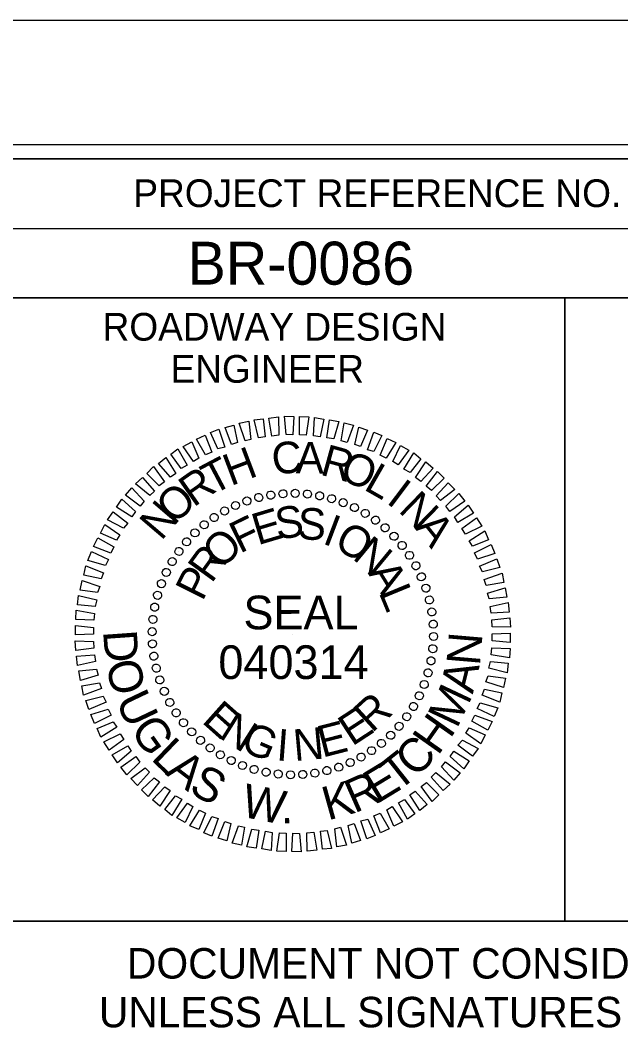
# Model space of a CAD drawing. Extents: x 10070 to 15319, y 8517 to 10343.
# Drawn here: x 14676.7 to 14785, y 9432.8 to 9616.7 of the extents above; entities that cross this region are included whole.
import ezdxf

# ---------------------------------------------------------------- set-up
doc = ezdxf.new("R2010")
doc.units = 0
for name, color, linetype in [('Scratch_Level_3', 7, 'Continuous'), ('Scratch_Level_4', 7, 'Continuous'), ('Sheet Cutting Line CELL', 7, 'Continuous'), ('Sheet Data Field CELL', 7, 'Continuous'), ('Sheet PE Seal Cell', 7, 'Continuous'), ('Sheet Plot Border Inside CELL', 7, 'Continuous'), ('Sheet Plot Border Outside CELL', 7, 'Continuous'), ('Sheet Profile CELL', 7, 'Continuous'), ('Sheet Profile Grid Major CELL', 7, 'Continuous'), ('Sheet Profile Grid Minor CELL', 7, 'Continuous'), ('Sheet Sticker Exception Certification CELL', 7, 'Continuous')]:
    doc.layers.add(name, color=color, linetype=linetype)

msp = doc.modelspace()

# ---------------------------------------------------------------- linework, layer by layer
at = {"layer": 'Scratch_Level_3'}
msp.add_lwpolyline([(13374.94, 9591.73), (14824.91, 9591.73), (14824.91, 8566.73), (13374.94, 8566.73)], close=True, dxfattribs=at)
at = {"layer": 'Scratch_Level_4'}
msp.add_lwpolyline([(13374.94, 9591.73), (14874.94, 9591.73), (14874.94, 9091.73), (13374.94, 9091.73)], close=True, dxfattribs=at)
at = {"layer": 'Sheet Cutting Line CELL'}
msp.add_line((14891.94, 9616.73), (13207.94, 9616.73), dxfattribs=at)
at = {"layer": 'Sheet PE Seal Cell'}
for p, q in [((14719.69, 9530.65), (14719.69, 9530.65)), ((14721.92, 9531.05), (14721.92, 9531.05)), ((14724.1, 9531.36), (14724.1, 9531.36)), ((14726.33, 9531.41), (14726.33, 9531.41)), ((14728.55, 9531.26), (14728.55, 9531.26)), ((14730.73, 9530.9), (14730.73, 9530.9)), ((14732.86, 9530.45), (14732.86, 9530.45)), ((14715.54, 9529.23), (14715.54, 9529.23)), ((14717.57, 9530.04), (14717.57, 9530.04)), ((14734.98, 9529.74), (14734.98, 9529.74)), ((14737.01, 9528.83), (14737.01, 9528.83)), ((14711.65, 9527.05), (14711.65, 9527.05)), ((14713.57, 9528.21), (14713.57, 9528.21)), ((14738.98, 9527.82), (14738.98, 9527.82)), ((14709.88, 9525.78), (14709.88, 9525.78)), ((14740.81, 9526.55), (14740.81, 9526.55)), ((14742.58, 9525.19), (14742.58, 9525.19)), ((14708.21, 9524.26), (14708.21, 9524.26)), ((14744.15, 9523.67), (14744.15, 9523.67)), ((14706.69, 9522.69), (14706.69, 9522.69)), ((14745.67, 9522), (14745.67, 9522)), ((14705.32, 9520.92), (14705.32, 9520.92)), ((14746.93, 9520.23), (14746.93, 9520.23)), ((14704.06, 9519.1), (14704.06, 9519.1)), ((14748.1, 9518.3), (14748.1, 9518.3)), ((14703.04, 9517.12), (14703.04, 9517.12)), ((14749.11, 9516.33), (14749.11, 9516.33)), ((14702.13, 9515.1), (14702.13, 9515.1)), ((14749.92, 9514.31), (14749.92, 9514.31)), ((14701.43, 9512.97), (14701.43, 9512.97)), ((14750.53, 9512.18), (14750.53, 9512.18)), ((14700.97, 9510.84), (14700.97, 9510.84)), ((14700.62, 9508.67), (14700.62, 9508.67)), ((14750.94, 9509.95), (14750.94, 9509.95)), ((14700.47, 9506.44), (14700.47, 9506.44)), ((14751.24, 9507.78), (14751.24, 9507.78)), ((14725.88, 9505.99), (14725.88, 9505.99)), ((14751.29, 9505.55), (14751.29, 9505.55)), ((14700.52, 9504.21), (14700.52, 9504.21)), ((14751.14, 9503.32), (14751.14, 9503.32)), ((14700.82, 9502.03), (14700.82, 9502.03)), ((14750.79, 9501.14), (14750.79, 9501.14)), ((14701.23, 9499.81), (14701.23, 9499.81)), ((14701.84, 9497.68), (14701.84, 9497.68)), ((14750.34, 9499.02), (14750.34, 9499.02)), ((14702.65, 9495.66), (14702.65, 9495.66)), ((14749.63, 9496.89), (14749.63, 9496.89)), ((14703.66, 9493.68), (14703.66, 9493.68)), ((14748.72, 9494.87), (14748.72, 9494.87)), ((14704.83, 9491.76), (14704.83, 9491.76)), ((14747.71, 9492.89), (14747.71, 9492.89)), ((14706.09, 9489.99), (14706.09, 9489.99)), ((14746.44, 9491.07), (14746.44, 9491.07)), ((14707.61, 9488.32), (14707.61, 9488.32)), ((14745.07, 9489.3), (14745.07, 9489.3)), ((14709.18, 9486.8), (14709.18, 9486.8)), ((14741.89, 9486.21), (14741.89, 9486.21)), ((14743.56, 9487.72), (14743.56, 9487.72)), ((14710.95, 9485.43), (14710.95, 9485.43)), ((14740.12, 9484.94), (14740.12, 9484.94)), ((14712.78, 9484.17), (14712.78, 9484.17)), ((14714.75, 9483.16), (14714.75, 9483.16)), ((14736.22, 9482.76), (14736.22, 9482.76)), ((14738.19, 9483.77), (14738.19, 9483.77)), ((14716.78, 9482.25), (14716.78, 9482.25)), ((14718.9, 9481.54), (14718.9, 9481.54)), ((14721.03, 9481.08), (14721.03, 9481.08)), ((14723.21, 9480.73), (14723.21, 9480.73)), ((14729.84, 9480.94), (14729.84, 9480.94)), ((14732.07, 9481.34), (14732.07, 9481.34)), ((14734.19, 9481.95), (14734.19, 9481.95)), ((14725.44, 9480.58), (14725.44, 9480.58)), ((14727.66, 9480.63), (14727.66, 9480.63))]:
    msp.add_line(p, q, dxfattribs=at)
for points in [[(14722.12, 9541.73), (14721.56, 9544.97), (14723.28, 9545.18), (14723.33, 9541.89)], [(14724.65, 9541.99), (14724.4, 9545.28), (14726.07, 9545.23), (14725.87, 9541.94)], [(14727.08, 9541.94), (14727.08, 9545.23), (14728.75, 9545.18), (14728.3, 9541.89)], [(14729.61, 9541.79), (14729.81, 9545.08), (14731.48, 9544.77), (14730.83, 9541.58)], [(14714.83, 9540.21), (14713.66, 9543.25), (14715.23, 9543.7), (14715.89, 9540.57)], [(14717.26, 9540.87), (14716.2, 9544.06), (14717.92, 9544.41), (14718.32, 9541.12)], [(14719.69, 9541.43), (14718.88, 9544.67), (14720.55, 9544.82), (14720.9, 9541.58)], [(14732.04, 9541.38), (14732.5, 9544.62), (14734.17, 9544.37), (14733.26, 9541.23)], [(14734.62, 9540.83), (14735.13, 9544.12), (14736.85, 9543.71), (14735.69, 9540.57)], [(14737.05, 9540.17), (14737.81, 9543.31), (14739.38, 9542.8), (14738.12, 9539.82)], [(14710.12, 9538.34), (14708.5, 9541.17), (14710.07, 9541.88), (14711.24, 9538.79)], [(14712.35, 9539.4), (14711.03, 9542.34), (14712.55, 9542.94), (14713.62, 9539.7)], [(14739.33, 9539.26), (14740.5, 9542.45), (14741.91, 9541.84), (14740.5, 9538.91)], [(14707.95, 9537.12), (14706.07, 9539.85), (14707.64, 9540.66), (14708.91, 9537.73)], [(14741.61, 9538.3), (14742.88, 9541.29), (14744.45, 9540.58), (14742.73, 9537.74)], [(14743.94, 9537.14), (14745.31, 9540.02), (14746.83, 9539.16), (14744.9, 9536.53)], [(14703.8, 9534.33), (14701.62, 9536.76), (14702.99, 9537.83), (14704.76, 9534.99)], [(14705.72, 9535.85), (14703.85, 9538.43), (14705.16, 9539.4), (14706.83, 9536.46)], [(14745.92, 9535.77), (14747.69, 9538.71), (14749, 9537.64), (14747.03, 9535.16)], [(14701.77, 9532.76), (14699.54, 9534.99), (14700.76, 9536.21), (14702.73, 9533.47)], [(14747.99, 9534.25), (14749.86, 9537.04), (14751.18, 9535.92), (14748.95, 9533.54)], [(14700.1, 9530.99), (14697.52, 9533.07), (14698.78, 9534.23), (14700.91, 9531.8)], [(14749.92, 9532.68), (14751.99, 9535.32), (14753.21, 9534.1), (14750.88, 9531.92)], [(14698.33, 9529.07), (14695.7, 9531.04), (14696.81, 9532.36), (14699.04, 9529.98)], [(14751.74, 9530.91), (14753.92, 9533.29), (14755.13, 9532.08), (14752.5, 9530.1)], [(14696.81, 9527.14), (14694.08, 9528.86), (14695.04, 9530.33), (14697.47, 9528.1)], [(14753.51, 9529.09), (14755.84, 9531.37), (14756.9, 9530), (14754.22, 9528.08)], [(14755.03, 9527.12), (14757.51, 9529.24), (14758.47, 9527.78), (14755.64, 9526.15)], [(14695.3, 9525.12), (14692.46, 9526.63), (14693.47, 9528.05), (14696.11, 9526.03)], [(14756.35, 9525.04), (14759.03, 9526.97), (14759.99, 9525.45), (14757.06, 9524.03)], [(14694.08, 9522.94), (14691.2, 9524.2), (14691.95, 9525.77), (14694.69, 9523.9)], [(14693.07, 9520.61), (14689.93, 9521.77), (14690.69, 9523.34), (14693.58, 9521.72)], [(14757.67, 9522.81), (14760.5, 9524.59), (14761.16, 9523.02), (14758.27, 9521.85)], [(14758.68, 9520.64), (14761.67, 9522.16), (14762.32, 9520.54), (14759.19, 9519.52)], [(14692.06, 9518.38), (14688.92, 9519.29), (14689.58, 9520.86), (14692.61, 9519.45)], [(14759.59, 9518.26), (14762.68, 9519.58), (14763.24, 9518.01), (14760.1, 9517.2)], [(14691.3, 9515.95), (14688.16, 9516.61), (14688.51, 9518.28), (14691.7, 9517.02)], [(14690.64, 9513.52), (14687.5, 9513.93), (14687.86, 9515.65), (14691.05, 9514.59)], [(14760.4, 9515.83), (14763.64, 9516.99), (14763.95, 9515.32), (14760.76, 9514.77)], [(14761.01, 9513.4), (14764.2, 9514.36), (14764.5, 9512.64), (14761.32, 9512.34)], [(14690.24, 9510.94), (14687, 9511.24), (14687.2, 9512.96), (14690.49, 9512.15)], [(14689.99, 9508.51), (14686.7, 9508.61), (14686.8, 9510.28), (14690.09, 9509.72)], [(14761.47, 9510.97), (14764.76, 9511.68), (14764.91, 9509.96), (14761.67, 9509.75)], [(14761.77, 9508.54), (14765.06, 9508.95), (14765.17, 9507.22), (14761.87, 9507.32)], [(14689.94, 9505.98), (14686.65, 9505.83), (14686.65, 9507.55), (14689.94, 9507.19)], [(14689.99, 9503.45), (14686.7, 9503.04), (14686.6, 9504.76), (14689.89, 9504.66)], [(14761.82, 9506.01), (14765.12, 9506.16), (14765.12, 9504.44), (14761.83, 9504.79)], [(14761.77, 9503.48), (14765.07, 9503.38), (14764.97, 9501.71), (14761.67, 9502.26)], [(14690.29, 9501.02), (14687, 9500.31), (14686.85, 9502.03), (14690.09, 9502.23)], [(14761.52, 9501.05), (14764.76, 9500.74), (14764.56, 9499.02), (14761.27, 9499.83)], [(14690.75, 9498.59), (14687.56, 9497.62), (14687.26, 9499.35), (14690.45, 9499.65)], [(14691.36, 9496.16), (14688.12, 9494.99), (14687.81, 9496.66), (14691, 9497.22)], [(14761.12, 9498.46), (14764.26, 9498.06), (14763.9, 9496.34), (14760.71, 9497.4)], [(14760.46, 9496.03), (14763.6, 9495.38), (14763.25, 9493.71), (14760.06, 9494.97)], [(14692.17, 9493.73), (14689.08, 9492.41), (14688.52, 9493.98), (14691.66, 9494.79)], [(14759.7, 9493.6), (14762.84, 9492.69), (14762.19, 9491.12), (14759.15, 9492.54)], [(14693.08, 9491.35), (14690.1, 9489.83), (14689.44, 9491.45), (14692.58, 9492.46)], [(14694.1, 9489.17), (14691.26, 9487.4), (14690.6, 9488.97), (14693.49, 9490.13)], [(14758.69, 9491.38), (14761.83, 9490.21), (14761.07, 9488.64), (14758.19, 9490.26)], [(14757.68, 9489.05), (14760.57, 9487.78), (14759.81, 9486.21), (14757.07, 9488.08)], [(14695.41, 9486.95), (14692.73, 9485.02), (14691.77, 9486.54), (14694.7, 9487.96)], [(14756.47, 9486.87), (14759.3, 9485.35), (14758.29, 9483.93), (14755.66, 9485.96)], [(14696.73, 9484.87), (14694.25, 9482.74), (14693.29, 9484.21), (14696.12, 9485.83)], [(14754.95, 9484.84), (14757.68, 9483.12), (14756.72, 9481.66), (14754.29, 9483.88)], [(14698.25, 9482.9), (14695.92, 9480.62), (14694.86, 9481.98), (14697.54, 9483.91)], [(14753.43, 9482.92), (14756.06, 9480.95), (14754.95, 9479.63), (14752.72, 9482.01)], [(14700.02, 9481.08), (14697.85, 9478.69), (14696.63, 9479.91), (14699.26, 9481.88)], [(14751.66, 9481), (14754.24, 9478.92), (14752.98, 9477.76), (14750.85, 9480.18)], [(14701.84, 9479.3), (14699.77, 9476.67), (14698.55, 9477.89), (14700.88, 9480.06)], [(14749.99, 9479.22), (14752.22, 9477), (14751, 9475.78), (14749.03, 9478.51)], [(14703.77, 9477.74), (14701.9, 9474.95), (14700.58, 9476.06), (14702.81, 9478.44)], [(14747.96, 9477.65), (14750.14, 9475.22), (14748.78, 9474.16), (14747, 9476.99)], [(14705.85, 9476.22), (14704.07, 9473.28), (14702.76, 9474.34), (14704.73, 9476.82)], [(14707.82, 9474.85), (14706.45, 9471.97), (14704.94, 9472.83), (14706.86, 9475.46)], [(14746.04, 9476.13), (14747.92, 9473.55), (14746.6, 9472.59), (14744.93, 9475.52)], [(14710.15, 9473.69), (14708.89, 9470.7), (14707.32, 9471.41), (14709.04, 9474.24)], [(14741.64, 9473.65), (14743.26, 9470.82), (14741.69, 9470.11), (14740.52, 9473.19)], [(14743.81, 9474.87), (14745.69, 9472.13), (14744.12, 9471.32), (14742.85, 9474.26)], [(14712.43, 9472.73), (14711.27, 9469.54), (14709.85, 9470.14), (14711.26, 9473.08)], [(14714.71, 9471.82), (14713.95, 9468.68), (14712.38, 9469.18), (14713.64, 9472.17)], [(14736.93, 9471.78), (14738.1, 9468.74), (14736.53, 9468.28), (14735.87, 9471.42)], [(14739.41, 9472.59), (14740.73, 9469.65), (14739.21, 9469.04), (14738.15, 9472.28)], [(14717.14, 9471.16), (14716.63, 9467.87), (14714.91, 9468.27), (14716.07, 9471.41)], [(14719.72, 9470.6), (14719.26, 9467.36), (14717.59, 9467.62), (14718.5, 9470.76)], [(14722.15, 9470.2), (14721.95, 9466.91), (14720.28, 9467.21), (14720.93, 9470.4)], [(14724.68, 9470.05), (14724.68, 9466.76), (14723.01, 9466.81), (14723.47, 9470.1)], [(14727.11, 9470), (14727.37, 9466.71), (14725.69, 9466.76), (14725.9, 9470.05)], [(14729.64, 9470.25), (14730.2, 9467.01), (14728.48, 9466.81), (14728.43, 9470.1)], [(14732.07, 9470.56), (14732.88, 9467.32), (14731.21, 9467.17), (14730.86, 9470.41)], [(14734.5, 9471.12), (14735.57, 9467.93), (14733.84, 9467.57), (14733.44, 9470.86)]]:
    msp.add_lwpolyline(points, close=True, dxfattribs=at)
for centre, major_axis in [((14717.6, 9530), (-0.238, 0.689)), ((14719.73, 9530.63), (-0.177, 0.707)), ((14721.9, 9531.07), (-0.114, 0.72)), ((14724.1, 9531.32), (-0.051, 0.727)), ((14726.31, 9531.38), (0.012, 0.729)), ((14728.52, 9531.25), (0.076, 0.725)), ((14730.72, 9530.92), (0.139, 0.716)), ((14732.87, 9530.41), (0.201, 0.701)), ((14734.97, 9529.7), (0.261, 0.681)), ((14713.56, 9528.2), (-0.354, 0.637)), ((14715.54, 9529.19), (-0.297, 0.666)), ((14737, 9528.82), (0.319, 0.655)), ((14738.95, 9527.77), (0.375, 0.625)), ((14711.67, 9527.04), (-0.408, 0.604)), ((14740.8, 9526.54), (0.428, 0.59)), ((14708.23, 9524.25), (-0.507, 0.524)), ((14709.89, 9525.72), (-0.459, 0.566)), ((14742.53, 9525.16), (0.478, 0.55)), ((14706.71, 9522.65), (-0.55, 0.478)), ((14744.14, 9523.64), (0.524, 0.507)), ((14705.33, 9520.91), (-0.59, 0.428)), ((14745.61, 9521.98), (0.566, 0.459)), ((14704.11, 9519.06), (-0.625, 0.375)), ((14746.93, 9520.2), (0.604, 0.408)), ((14703.05, 9517.12), (-0.655, 0.319)), ((14748.09, 9518.31), (0.637, 0.354)), ((14702.17, 9515.08), (-0.681, 0.261)), ((14749.07, 9516.33), (0.666, 0.297)), ((14701.47, 9512.98), (-0.701, 0.201)), ((14749.89, 9514.27), (0.689, 0.238)), ((14750.52, 9512.15), (0.707, 0.177)), ((14700.95, 9510.83), (-0.716, 0.139)), ((14750.96, 9509.98), (0.72, 0.114)), ((14700.63, 9508.64), (-0.725, 0.076)), ((14751.21, 9507.78), (0.727, 0.051)), ((14700.49, 9506.43), (-0.729, 0.012)), ((14700.55, 9504.21), (-0.727, -0.051)), ((14751.27, 9505.56), (0.729, -0.012)), ((14700.8, 9502.01), (-0.72, -0.114)), ((14751.14, 9503.35), (0.725, -0.076)), ((14750.81, 9501.16), (0.716, -0.139)), ((14701.24, 9499.84), (-0.707, -0.177)), ((14750.29, 9499), (0.701, -0.201)), ((14701.87, 9497.72), (-0.689, -0.238)), ((14749.59, 9496.9), (0.681, -0.261)), ((14702.69, 9495.66), (-0.666, -0.297)), ((14748.71, 9494.87), (0.655, -0.319)), ((14703.68, 9493.67), (-0.637, -0.354)), ((14747.65, 9492.92), (0.625, -0.375)), ((14704.83, 9491.78), (-0.604, -0.408)), ((14746.43, 9491.08), (0.59, -0.428)), ((14706.15, 9490), (-0.566, -0.459)), ((14745.05, 9489.34), (0.55, -0.478)), ((14707.62, 9488.35), (-0.524, -0.507)), ((14743.53, 9487.73), (0.507, -0.524)), ((14709.23, 9486.82), (-0.478, -0.55)), ((14710.96, 9485.44), (-0.428, -0.59)), ((14741.87, 9486.27), (0.459, -0.566)), ((14712.81, 9484.22), (-0.375, -0.625)), ((14738.2, 9483.79), (0.354, -0.637)), ((14740.09, 9484.95), (0.408, -0.604)), ((14714.76, 9483.17), (-0.319, -0.655)), ((14716.79, 9482.28), (-0.261, -0.681)), ((14734.16, 9481.99), (0.238, -0.689)), ((14736.22, 9482.8), (0.297, -0.666)), ((14718.89, 9481.58), (-0.201, -0.701)), ((14721.05, 9481.06), (-0.139, -0.716)), ((14723.24, 9480.74), (-0.076, -0.725)), ((14725.45, 9480.6), (-0.012, -0.729)), ((14727.66, 9480.66), (0.051, -0.727)), ((14729.86, 9480.91), (0.114, -0.72)), ((14732.03, 9481.36), (0.177, -0.707))]:
    msp.add_ellipse(centre, major_axis=major_axis, ratio=0.999708, dxfattribs=at)
at = {"layer": 'Sheet Plot Border Inside CELL'}
msp.add_lwpolyline([(13220.94, 8539.18), (14887.44, 8539.18), (14887.44, 9594.28), (13220.94, 9594.28)], close=True, dxfattribs=at)
at = {"layer": 'Sheet Plot Border Outside CELL'}
msp.add_lwpolyline([(13207.94, 8516.73), (14891.94, 8516.73), (14891.94, 9616.73), (13207.94, 9616.73)], close=True, dxfattribs=at)
at = {"layer": 'Sheet Profile CELL'}
for p, q in [((14674.89, 9579.18), (14874.94, 9579.18)), ((14774.94, 9566.68), (14774.94, 9454.23))]:
    msp.add_line(p, q, dxfattribs=at)
for points in [[(14874.94, 9591.73), (13374.94, 9591.73), (13374.94, 8541.73), (14874.94, 8541.73)], [(14674.89, 9591.73), (14874.94, 9591.73), (14874.94, 9566.68), (14674.89, 9566.68)], [(14674.89, 9566.68), (14774.94, 9566.68), (14774.94, 9454.18), (14674.89, 9454.18)], [(14774.94, 9566.68), (14874.94, 9566.68), (14874.94, 9454.18), (14774.94, 9454.18)]]:
    msp.add_lwpolyline(points, close=True, dxfattribs=at)
at = {"layer": 'Sheet Profile Grid Major CELL'}
msp.add_lwpolyline([(14224.94, 9091.73), (14274.94, 9091.73), (14274.94, 9591.73), (14324.94, 9591.73), (14324.94, 9091.73), (14374.94, 9091.73), (14374.94, 9591.73), (14424.94, 9591.73), (14424.94, 9091.73), (14474.94, 9091.73), (14474.94, 9591.73), (14524.94, 9591.73), (14524.94, 9091.73), (14574.94, 9091.73), (14574.94, 9591.73), (14624.94, 9591.73), (14624.94, 9091.73), (14674.94, 9091.73), (14674.94, 9591.73), (14701.24, 9591.73)], dxfattribs=at)
at = {"layer": 'Sheet Profile Grid Minor CELL'}
msp.add_lwpolyline([(14669.94, 9591.73), (14679.94, 9591.73)], dxfattribs=at)
at = {"layer": 'Sheet Sticker Exception Certification CELL'}
msp.add_line((14674.89, 9454.18), (14874.93, 9454.18), dxfattribs=at)
msp.add_line((14674.89, 9454.18), (14874.93, 9454.18), dxfattribs=at)

# ---------------------------------------------------------------- texts
at = {"layer": 'Sheet Data Field CELL'}
msp.add_text('BR-0086', height=7.75, dxfattribs=at).set_placement((14706.87, 9569.04))
at = {"layer": 'Sheet PE Seal Cell'}
for s, height, rotation, p in [('H', 5.71, 20.6431, (14714.68, 9532.67)), ('C', 5.71, 6.2435, (14722.38, 9534.7)), ('A', 5.71, 359.044, (14726.38, 9535)), ('R', 5.71, 344.6448, (14730.63, 9534.8)), ('T', 5.71, 27.8434, (14711.39, 9531)), ('O', 5.71, 337.4448, (14734.02, 9534.04)), ('L', 5.71, 330.2445, (14738.48, 9532.17)), ('R', 5.71, 35.0442, (14707.95, 9528.77)), ('O', 5.71, 42.2454, (14704.46, 9525.63)), ('I', 5.71, 323.0438, (14742.58, 9529.74)), ('N', 5.71, 315.8426, (14744.75, 9528.17)), ('N', 5.71, 49.4472, (14702.13, 9522.69)), ('E', 5.71, 16.6347, (14719.55, 9521.99)), ('S', 5.71, 7.2793, (14723.04, 9523.05)), ('S', 5.71, 357.9241, (14726.68, 9523.1)), ('F', 5.71, 25.9907, (14716.31, 9520.47)), ('I', 5.71, 339.2133, (14731.04, 9522.4)), ('A', 5.71, 308.6408, (14747.74, 9525.19)), ('O', 5.71, 329.8571, (14733.06, 9521.69)), ('O', 5.71, 44.7049, (14712.97, 9517.48)), ('N', 5.71, 320.5003, (14736.46, 9519.67)), ('R', 5.71, 54.0633, (14711.2, 9515)), ('P', 5.71, 63.4226, (14709.58, 9511.76)), ('A', 5.71, 301.7839, (14739.34, 9517.04)), ('L', 5.71, 292.4245, (14741.32, 9513.54)), ('SEAL', 6.073, 0.0237, (14716.97, 9506.85)), ('D', 6.07, 274.0393, (14691.64, 9506.52)), ('N', 6.07, 85.158, (14759.63, 9500.18)), ('040314', 6.073, 0.0237, (14712.45, 9497.88)), ('O', 6.07, 283.9151, (14692.05, 9500.64)), ('A', 6.07, 76.3177, (14758.34, 9495.06)), ('U', 6.07, 295.4755, (14693.81, 9493.97)), ('M', 6.07, 64.7882, (14755.5, 9488.8)), ('E', 5.71, 318.3006, (14709.28, 9490.14)), ('R', 5.71, 42.5051, (14740.16, 9488.03)), ('N', 5.71, 327.6576, (14712.32, 9487.41)), ('E', 5.71, 33.1478, (14736.57, 9485.65)), ('G', 6.07, 305.4131, (14696.37, 9488.62)), ('E', 5.71, 14.4354, (14731.21, 9483.67)), ('H', 6.07, 54.8042, (14752.07, 9483.92)), ('G', 5.71, 337.0139, (14716.17, 9485.13)), ('I', 5.71, 355.7249, (14722.8, 9483.21)), ('N', 5.71, 5.0801, (14726.19, 9483.06)), ('L', 6.07, 316.139, (14700.12, 9483.43)), ('C', 6.07, 45.2221, (14748.03, 9479.87)), ('T', 6.07, 38.4218, (14744.78, 9477.43)), ('A', 6.07, 322.4137, (14702.74, 9480.75)), ('E', 6.07, 31.3125, (14741.1, 9475.31)), ('S', 6.07, 331.254, (14706.89, 9477.49)), ('R', 6.07, 23.8322, (14736.98, 9473.59)), ('W', 6.07, 348.7801, (14716.36, 9473.1)), ('K', 6.07, 15.5483, (14732.19, 9472.33)), ('.', 6.07, 1.3142, (14723.72, 9471.81))]:
    msp.add_text(s, height=height, rotation=rotation, dxfattribs=at).set_placement(p)
at = {"layer": 'Sheet Profile CELL'}
for s, height, p in [('PROJECT REFERENCE NO.', 5.0001, (14697.1, 9583.04)), ('ROADWAY DESIGN', 5.0001, (14691.55, 9558.94)), ('ENGINEER', 5, (14703.8, 9551.34))]:
    msp.add_text(s, height=height, dxfattribs=at).set_placement(p)
at = {"layer": 'Sheet Sticker Exception Certification CELL'}
for s, p in [('DOCUMENT NOT CONSIDERED FINAL', (14695.96, 9443.83)), ('DOCUMENT NOT CONSIDERED FINAL', (14695.96, 9443.83)), ('UNLESS ALL SIGNATURES COMPLETED', (14690.89, 9435.03)), ('UNLESS ALL SIGNATURES COMPLETED', (14690.89, 9435.03))]:
    msp.add_text(s, height=5.5, dxfattribs=at).set_placement(p)

doc.saveas('drawing.dxf')
